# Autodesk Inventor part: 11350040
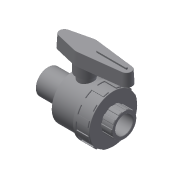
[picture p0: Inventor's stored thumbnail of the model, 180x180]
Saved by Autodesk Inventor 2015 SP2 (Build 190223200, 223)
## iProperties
Created: 2017-11
Part Number: 11350040
Material: Generic
Description: PLASSON 1/NUT VALVE CEM. PVC 40
Document SubType Name: Modeling
Designer: KIM
Density: 1 g/cm^3
Appearance: Default
Author: KIM
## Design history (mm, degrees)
derived "113500.ipt"
feature "Solid1::113500.ipt"
tag "TaggingFeature1"
body "Solid1"
other parameters: "d0" = 116, "d4" = 32, "d8" = 72, "d13" = 1.2, "d25" = 0.8, "d26" = 1.2, "d29" = 19.5, "d30" = 0, "d35" = 1.2, "d45" = 360 deg, "d47" = 0.8, "d50" = 44, "d51" = 24, "d53" = 0, "d55" = 8, "d56" = 4, "d57" = 18.2, "d58" = 0, "d59" = 1.2, "d63" = 32, "d64" = 74, "d66" = 96, "d68" = 16, "d69" = 28.8, "d70" = 18.5, "d71" = 3 deg, "d73" = 1.6, "d74" = 38.4, "d75" = 2.22, "d76" = 0, "d77" = 0.8, "d79" = 26, "d81" = 26, "d82" = 76.8, "d83" = 18.2, "d84" = 56, "d86" = 56, "d87" = 120 deg, "d88" = 26, "d90" = 360 deg, "d92" = 12, "d95" = 6, "l_" = 26, "H_" = 116, "F_" = 74, "J_" = 96, "d67" = 32, "d72" = 8
